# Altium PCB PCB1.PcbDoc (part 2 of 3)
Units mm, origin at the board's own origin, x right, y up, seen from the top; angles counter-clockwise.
Board outline 200.72 x 147.2 mm, 4 copper layers (L1 - TOP, L2 - GND, L3 - PWR, L4 - BOTTOM), stack 1.251 mm thick; 298 components, 161 nets, 911 pads, 474 vias.
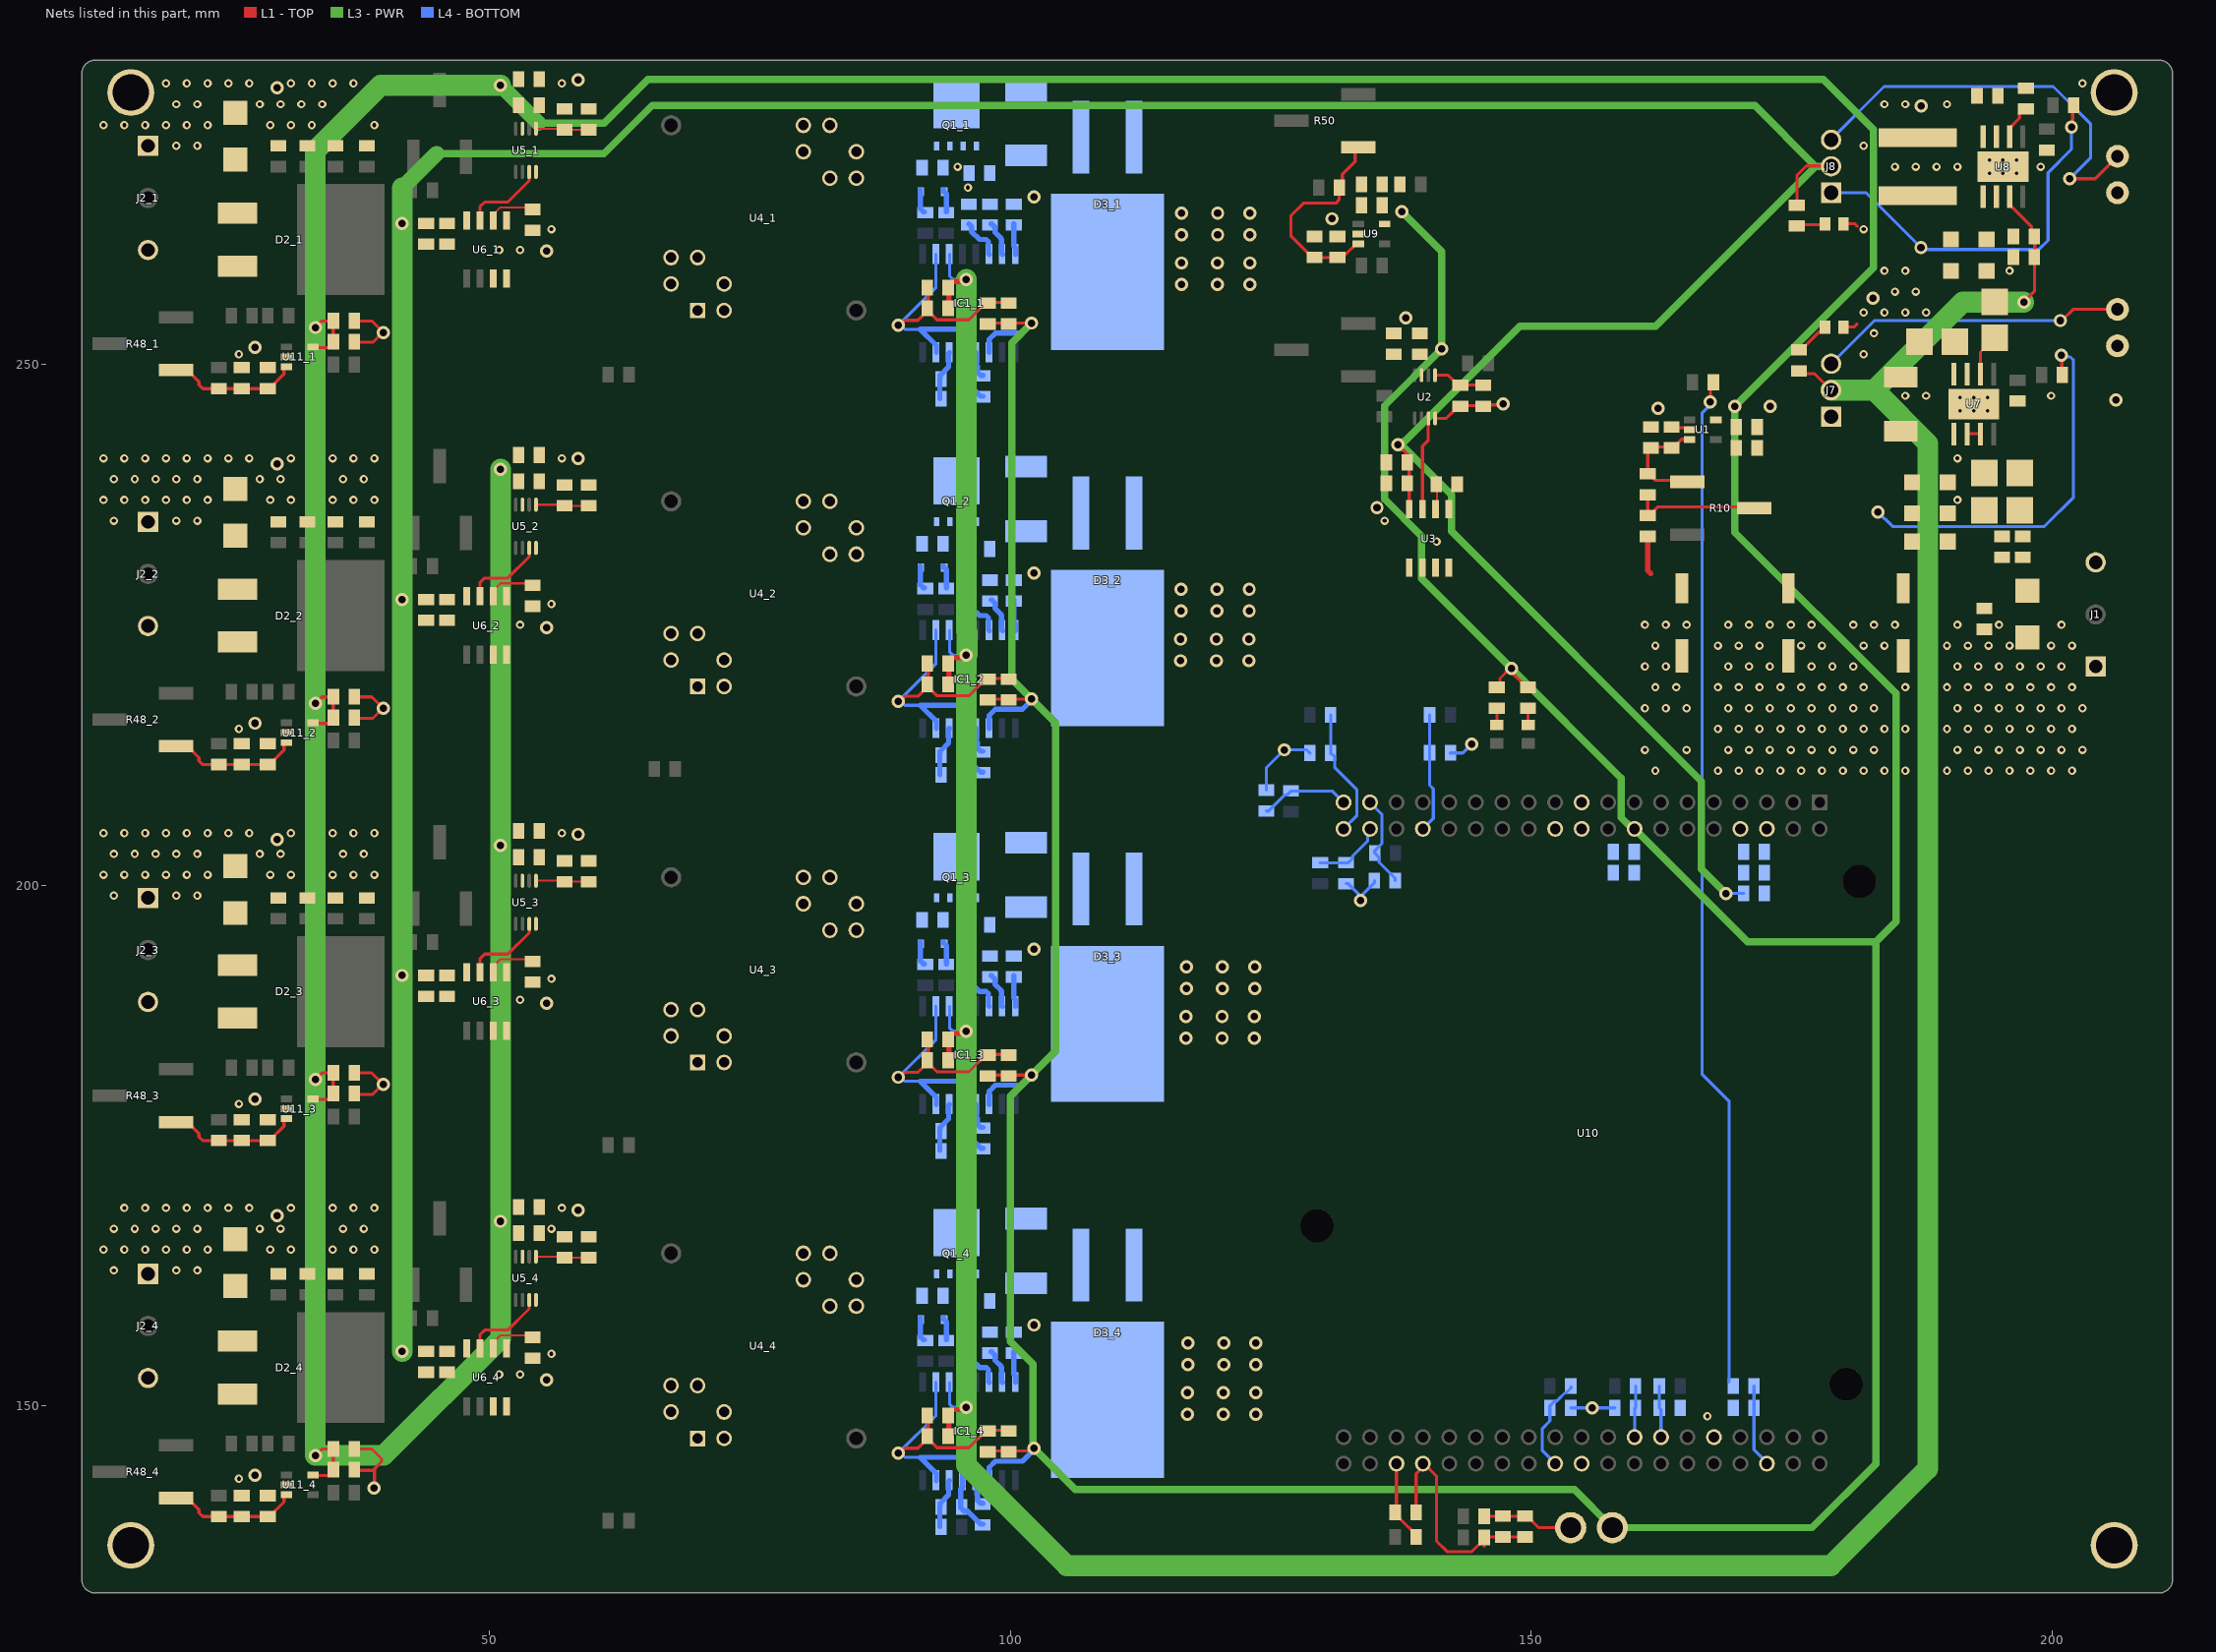
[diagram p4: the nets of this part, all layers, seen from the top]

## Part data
C1 C2 C3: "22uF 100V 121mA@120Hz ±20% SMD, D8xL10mm Aluminum Electrolytic Capacitors - SMD ROHS", Case/Package=3333, Leakage Current=66µA, Manufacturer="KYOCERA AVX", Manufacturer Part Number=UUX2A220MNL6GS, Max Operating Temperature=105°C, Min Operating Temperature=-55°C, Ratings=AEC-Q200, Ripple Current=121mA, Tolerance=20%, Voltage Rating=100V
C4 C5 C6 C7 C8 C9 C10 C11 C12 C13 C14 C15 C16 C17 C18_1 C18_2 C18_3 C18_4 C19_1 C19_2 C19_3 C19_4 C20_1 C20_2 C20_3 C20_4 C21_1 C21_2 C21_3 C21_4 C22_1 C22_2 C22_3 C22_4 C23_1 C23_2 C23_3 C23_4 C24_1 C24_2 C24_3 C24_4 C25_1 C25_2 C25_3 C25_4 C26_1 C26_2 C26_3 C26_4 C27_1 C27_2 C27_3 C27_4 C28_1 C28_2 C28_3 C28_4 C29_1 C29_2 C29_3 C29_4 C30_1 C30_2 C30_3 C30_4 C31_1 C31_2 C31_3 C31_4 C32_1 C32_2 C32_3 C32_4 C33_1 C33_2 C33_3 C33_4 C34_1 C34_2 C34_3 C34_4 C35_1 C35_2 C35_3 C35_4 C36_1 C36_2 C36_3 C36_4 C37_1 C37_2 C37_3 C37_4 C38_1 C38_2 C38_3 C38_4 C39 C40 C41 C42 C43 C44 C45 C46 C47 C48 C49 C50 C51 C52 C53 C54 C55 C56 C57 C58 C59 C60: "C0G Ceramic Smd Ceramic Capacitor"
D1: library part TVS_DIODE, "DIODO SMB"
D2_1 D2_2 D2_3 D2_4: "Rectifier Diode Schottky 40V 20A 3-Pin(2+Tab) D2PAK T/R", Manufacturer=Diotec, Manufacturer Lifecycle Status=ACTIVE, Manufacturer Part Number=SK2040YD2R
D3_1 D3_2 D3_3 D3_4 D5_1 D5_2 D5_3 D5_4: "DIODO SMB"
D4_1 D4_2 D4_3 D4_4: "Schottky Barrier Diode, 2-Pin SOD-323, Pb-Free, Tape and Reel", Manufacturer="On Semiconductor"
D6 D7 D8 D9: "DIODO LED 20mA 0805", Case Code (Imperial)=0805, Case Code (Metric)=2012, Color=Orange, Forward Current=25mA, Forward Voltage=2V, Lens Color=White, Manufacturer="Osram Opto", Manufacturer Part Number=LOR976-PS-1, Max Operating Temperature=85°C, Min Operating Temperature=-30°C, Package Quantity=16000, Reverse Voltage=12V, Supplier Part Number 1=475-2488-1-ND, Test Current=20mA
IC1_1 IC1_2 IC1_3 IC1_4: library part IR2110S, "500 V high-side and low-side gate driver IC with shutdown, SOIC 16W, RoHS", Case/Package=SOP, Manufacturer=Infineon, Manufacturer Part Number=IR2110STRPBF, Max Operating Temperature=125°C, Max Output current=2.5A, Max Output Voltage=20V, Max Power Dissipation=1.25W, Max Supply Current=340µA, Min Operating Temperature=-40°C, Min Output Voltage=10V, Min Supply Voltage=3.3V, Nominal Supply Voltage (DC)=15V, Output Voltage=520V, Package Quantity=1000, Supplier Part Number 1=IR2110SPBF, Temperature Grade=Automotive
J1 J2_1 J2_2 J2_3 J2_4: "Connector", Arrow Part Number=1935174, Manufacturer_Name="Phoenix Contact", Mouser Part Number=651-1935174
J3 J4: Manufacturer="CUI Devices", Manufacturer Part Number=TB005-762-02BE, Supplier Part Number 1=490-TB005-762-02BE
J7 J8: "Connector", Arrow Part Number=TSW-103-07-G-S-001, Manufacturer_Name=SAMTEC, Mouser Part Number=200-TSW10307GS001
Q1_1 Q1_2 Q1_3 Q1_4: library part BSC110N15NS5ATMA1_1, "Mosfet, N-Ch, 150V, 76A, Tdson Rohs Compliant: Yes", Continuous Drain Current=76A, Drain To Source Breakdown Voltage=150V, Drain To Source Resistance=9mΩ, Gate To Source Voltage=20V, Input Capacitace At Vds="2080pF @ 75V", Input Capacitance=2.08nF, Manufacturer=Infineon, Max Forward Diode Voltage=1.2V, Max Junction Temp=+150°C, Max Junction Temperature (Tj)=150°C, Max Power Dissipation=125W, Min Operating Temperature=-55°C, On-State Resistance=11mΩ, Package=PG-TDSON-8, Package Quantity=5000, Pulse Drain Current=304A, Temperature="-55°C to +150°C", Typ Forward Diode Voltage=0.88V
R1 R2 R3 R4 R5 R6 R7 R8 R9 R12_1 R12_2 R12_3 R12_4 R13_1 R13_2 R13_3 R13_4 R14_1 R14_2 R14_3 R14_4 R15_1 R15_2 R15_3 R15_4 R16_1 R16_2 R16_3 R16_4 R17_1 R17_2 R17_3 R17_4 R18_1 R18_2 R18_3 R18_4 R19_1 R19_2 R19_3 R19_4 R20_1 R20_2 R20_3 R20_4 R21_1 R21_2 R21_3 R21_4 R22_1 R22_2 R22_3 R22_4 R23_1 R23_2 R23_3 R23_4 R24_1 R24_2 R24_3 R24_4 R25_1 R25_2 R25_3 R25_4 R26_1 R26_2 R26_3 R26_4 R27_1 R27_2 R27_3 R27_4 R28_1 R28_2 R28_3 R28_4 R30_1 R30_2 R30_3 R30_4 R31 R32 R33 R34 R35 R36 R37 R38 R39 R40 R41 R42 R43 R44 R45: "SMD 0805 RESISTOR"
R10 R11 R48_1 R48_2 R48_3 R48_4 R50: library part TRIMPOT_3361_14INCH, "Trimmer, Cermet, 0.5W, 100000ohm, 300V, 10% +/-Tol, 100ppm/Cel, 1 Turn(s), 2826", Case/Package=2826, Color=Natural, Manufacturer=Bourns, Manufacturer Part Number=3361P-1-503GLF, Max Operating Temperature=125°C, Max Power Dissipation=500mW, Min Operating Temperature=-55°C, Supplier Part Number=1814483, Temperature Coefficient=100ppm/°C, Tolerance=10%, Voltage Rating=300V
R46: library part R_FL, "Resistor for flying wires"
R47_1 R47_2 R47_3 R47_4: "SMD 2512 RESISTOR"
R49_1 R49_2 R49_3 R49_4: library part TRIMPOT_3361_14INCH, "Trimmer, Cermet, 0.5W, 1000ohm, 300V, 10% +/-Tol, 100ppm/Cel, 1 Turn(s), 2619", Case/Package=2826, Color=Natural, Manufacturer=Bourns, Manufacturer Part Number=3361P-1-503GLF, Max Operating Temperature=125°C, Max Power Dissipation=500mW, Min Operating Temperature=-55°C, Supplier Part Number=1814483, Temperature Coefficient=100ppm/°C, Tolerance=10%, Voltage Rating=300V
U1: library part TLV9151_SOT23-5, "Operational Amplifier, 1 Func, 750uV Offset-Max", Manufacturer="Texas Instruments", Manufacturer Part Number=TLV9151IDBVR, Supplier Part Number 1=296-TLV9151IDBVRCT-ND
U2 U5_1 U5_2 U5_3 U5_4: library part INA326EA/250, "Precision, Low Drift, CMOS Instrumentation Amplifier 8-VSSOP -40 to 85", Case/Package=VSSOP, Input Bias Current=2nA, Input Bias Current (+/-)(Max)(nA)=2, Input Offset Voltage (Vos)=100µV, Manufacturer="Texas Instruments", Manufacturer Lifecycle Status=ACTIVE, Max Operating Temperature=85°C, Max Supply Voltage=5.5V, Min Operating Temperature=-40°C, Min Supply Voltage=2.7V, Nominal Supply Current=3.4mA, Operating Supply Current=2.4mA, Output Current per Channel=25mA, Power Supply Rejection Ratio (PSRR)=93.98dB, Quiescent Current (+/-)(Typ)(mA)=2.4, Supplier Part Number=595-INA326EA/250G4, Supplier Part Number 1=INA326EA/2K5CT-ND, Voltage Gain=80dB
U3 U6_1 U6_2 U6_3 U6_4: "66 5", Ambient Temperature Range High=85°C, Case/Package=SOIC, Current Sensing=30A, Frequency=80kHz, Manufacturer="Allegro MicroSystems", Max Junction Temperature (Tj)=165°C, Max Supply Current=13mA, Max Supply Voltage=5.5V, Min Operating Temperature=-40°C, Min Supply Voltage=4.5V, Operating Supply Current=10mA, Operating Supply Voltage=5V, Output Voltage=8V, Package Quantity=1
U4_1 U4_2 U4_3 U4_4: "Power Inductor", Arrow Part Number=B65812N1012D001, Manufacturer_Name=TDK, Mouser Part Number=871-B65812N1012D1
U7 U8: "Switching Regulator, Current-mode, 1A, 460kHz Switching Freq-Max, BICMOS, PDSO8", Manufacturer="Texas Instruments", Manufacturer Lifecycle Status=ACTIVE, Max Junction Temperature (Tj)=150°C, Max Operating Temperature=125°C, Max Supply Voltage=65V, Min Operating Temperature=-40°C, Min Supply Voltage=4.2V, Nominal Supply Current=26µA, Output Current=1A, Supplier Part Number=296-LMR36510ADDARCT-ND, Supplier Part Number 1=296-LMR36510ADDARDKR-ND, Switching Frequency=400kHz
U9 U11_1 U11_2 U11_3 U11_4: library part TLV9151_SOT23-5, "Operational Amplifier, 1 Func, 750uV Offset-Max", Manufacturer="Texas Instruments", Manufacturer Part Number=TLV9151IDBVR, Supplier Part Number 1=595-TLV9151IDBVR
U10: library part NUCLEO-F072RB, "STM32F072RB, mbed-Enabled Development Nucleo-64 STM32F0 ARMÂ® CortexÂ®-M0 MCU 32-Bit Embedded Evaluation Board", Package=None
U12: "Inductor Power Shielded Wirewound 47uH 30% 100KHz 14Q-Factor Ferrite 1.2A 0.177Ohm DCR 3131 T/R", Arrow Part Number=B65812N1012D001, Case/Package=3131, Current Rating=1.2A, DC Resistance (DCR)=177mΩ, Inductance Tolerance=30%, Manufacturer=Bourns, Manufacturer Part Number=SRU8028-470Y, Manufacturer_Name=TDK, Max Operating Temperature=125°C, Min Operating Temperature=-40°C, Mouser Part Number=871-B65812N1012D1, Saturation Current=1A, Self Resonant Frequency=12MHz, Test Frequency=100kHz
U13: library part NRS8040T220MJGJ, "Shielded Wirewound Inductor 22uH 20% 2.6A 85.8mΩ SMD Automotive", Case/Package=Nonstandard, Current Rating=2.2A, DC Resistance (DCR)=85.8mR, Inductance=22uH, Max Operating Temperature=125°C, Min Operating Temperature=-40°C, Package Quantity=1000, Ratings=AEC-Q200, Resistor Type=Wirewound, Saturation Current=2.4A, Self Resonant Frequency=13MHz, Test Frequency=100kHz, Tolerance=20%

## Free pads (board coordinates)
  round 4.5 hole 3.5: MH(15.55,136.6) MH(15.55,276.125) MH(205.975,136.6) MH(205.975,276.125)

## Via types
v1: diameter 0.8, hole 0.4, L1 - TOP to L4 - BOTTOM, tented both sides, 312 vias
v2: diameter 1.27, hole 0.711, L1 - TOP to L4 - BOTTOM, 150 vias
v3: diameter 0.63, hole 0.33, L1 - TOP to L4 - BOTTOM, 12 vias

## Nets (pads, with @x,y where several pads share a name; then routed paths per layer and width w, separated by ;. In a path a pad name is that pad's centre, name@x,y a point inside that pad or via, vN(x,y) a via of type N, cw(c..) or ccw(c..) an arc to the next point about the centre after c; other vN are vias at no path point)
3V3: C7.1 C8.1 C11.1 C12.1 C23_1.1 C23_2.1 C23_3.1 C23_4.1 C24_1.1 C24_2.1 C24_3.1 C24_4.1 C25_1.1 C25_2.1 C25_3.1 C25_4.1 C26_1.1 C26_2.1 C26_3.1 C26_4.1 C31_1.2 C31_2.2 C31_3.2 C31_4.2 C32_1.2 C32_2.2 C32_3.2 C32_4.2 C47.1 C48.1 C57.2 C58.2 IC1_1.11 IC1_2.11 IC1_3.11 IC1_4.11 R33.2 R40.1 R43.1 R46.1 U1.5 U2.7 U5_1.7 U5_2.7 U5_3.7 U5_4.7 U9.5 U10.CN7_16 U11_1.5 U11_2.5 U11_3.5 U11_4.5 | length 908
  L1 - TOP w0.3: U11_4.5@33.098,143.309 34.683,143.309 34.983,143.609 34.983,145.856 33.907,145.856 33.282,145.231 v2(33.258,145.231) ; U11_3.5@33.098,179.419 34.683,179.419 34.983,179.719 34.983,181.966 33.907,181.966 33.282,181.341 v2(33.258,181.341) ; U11_2.5@33.098,215.529 34.683,215.529 34.983,215.829 34.983,218.076 33.907,218.076 33.282,217.451 v2(33.258,217.451) ; U11_1.5@33.098,251.639 34.683,251.639 34.983,251.939 34.983,254.186 33.907,254.186 33.282,253.561 v2(33.258,253.561) ; C31_4.2@97.833,145.656 99.858,145.656 cw(c99.858,145.631) C32_4.2@99.883,145.631 ; C31_3.2@97.833,181.766 C32_3.2@99.858,181.766 ; C31_2.2@97.833,217.876 C32_2.2@99.858,217.876 ; C31_1.2@97.833,253.986 C32_1.2@99.858,253.986 ; C31_3.2@97.858,181.766 C32_3.2@99.858,181.766 ; C31_2.2@97.858,217.876 C32_2.2@99.858,217.876 ; C31_1.2@97.858,253.986 C32_1.2@99.858,253.986 ; C32_4.2@99.883,145.656 101.623,145.656 101.689,145.722 102.099,145.722 v2(102.284,145.907) ; C32_3.2@99.883,181.741 ccw(c99.858,181.741) C32_3.2@99.858,181.766 ; C32_2.2@99.883,217.851 ccw(c99.858,217.851) C32_2.2@99.858,217.876 ; C32_1.2@99.883,253.961 ccw(c99.858,253.961) C32_1.2@99.858,253.986 ; v2(102.033,181.766) C32_3.2@99.858,181.766 ; v2(102.033,217.876) C32_2.2@99.858,217.876 ; v2(102.033,253.986) C32_1.2@99.858,253.986 ; R43.1@146.708,219.046 147,219.338 147,219.849 147.951,220.8 v2(148.125,220.8) 148.311,220.614 148.311,220.255 149.096,219.469 149.096,219.446 149.496,219.046 R40.1@149.708,219.046
  L3 - PWR w0.7: 54.665,273.2 61,273.2 65.2,277.4 178.051,277.4 182.875,272.576 182.875,259.3 v2(169.55,245.975) 169.55,233.877 185.025,218.402 185.025,196.5 183.1,194.575 ; v2(102.033,253.986) 100.125,252.078 100.125,219.784 v2(102.033,217.876) 104.35,215.559 104.35,184.083 v2(102.033,181.766) 100,179.733 100,156.175 102.175,154 102.175,146.016 106.241,141.95 154.15,141.95 R46.1@157.8,138.3 176.975,138.3 183.1,144.425 183.1,194.575 ; v2(137.575,264.7) 141.4,260.875 v2(141.4,251.5) 135.95,246.05 135.95,237.05 139.475,233.525 139.475,229.45 v2(148.125,220.8) 158.625,210.3 158.625,206.5 159.715,205.41 U10.CN7_16@159.93,205.41 170.765,194.575 183.1,194.575
  L3 - PWR w1.5: v2(51.05,276.815) 54.665,273.2
  L3 - PWR w2: v2(51.05,239.94) v2(51.05,203.83) v2(51.05,167.72) 51.05,156.45 39.831,145.231 v2(33.258,145.231) v2(33.258,181.341) v2(33.258,217.451) v2(33.258,253.561) 33.258,270.533 39.54,276.815 v2(51.05,276.815)
  L4 - BOTTOM w0.5: IC1_4.11@97.963,142.822 97.963,144.086 98.558,144.681 101.158,144.681 102.284,145.807 v2(102.284,145.907) ; IC1_3.11@97.963,178.932 97.963,180.196 98.558,180.791 101.158,180.791 102.033,181.666 v2(102.033,181.766) ; IC1_2.11@97.963,215.042 97.963,216.306 98.558,216.901 101.158,216.901 102.033,217.776 v2(102.033,217.876) ; IC1_1.11@97.963,251.152 97.963,252.416 98.558,253.011 101.158,253.011 102.033,253.886 v2(102.033,253.986)
+5V: C14.1 C15.1 C33_1.1 C33_2.1 C33_3.1 C33_4.1 C34_1.1 C34_2.1 C34_3.1 C34_4.1 J8.2 R39.2 R45.1 U3.8 U6_1.8 U6_2.8 U6_3.8 U6_4.8 | length 376.9
  L1 - TOP w0.3: v2(137.2,242.3) 138.295,241.205 U3.8@138.295,236.1 ; R45.1@175.525,265.35 175.525,268.175 176.425,269.075 J8.2@178.8,269.075
  L3 - PWR w0.7: 44.901,270.25 60.976,270.25 65.601,274.875 171.476,274.875 177.311,269.04 ; v2(137.2,242.3) v2@137.526,242.3 ; v2(168.7,199.2) 166.348,201.552 166.348,209.977 142.351,233.974 142.351,237.475 137.811,242.015 137.639,242.015 137.463,242.191 137.463,242.409 137.639,242.585 137.811,242.585 148.901,253.675 161.946,253.675 177.311,269.04 ; J8.2@178.799,269.04 177.311,269.04
  L3 - PWR w1.5: 41.6,266.949 44.901,270.25
  L3 - PWR w2: v2(41.6,155.22) v2(41.6,227.44) v2(41.6,263.55) 41.6,266.949
  L4 - BOTTOM w0.3: v2(168.7,199.2) R39.2@170.4,199.2
  other v2: 41.6,191.33
+12V: C36_1.1 C36_2.1 C36_3.1 C36_4.1 C37_1.1 C37_2.1 C37_3.1 C37_4.1 C53.2 C54.2 IC1_1.3 IC1_2.3 IC1_3.3 IC1_4.3 J7.2 R41.1 U8.2 U8.3 | length 387.9
  L1 - TOP w0.3: R41.1@175.7,249.4 175.984,249.116 177.224,249.116 J7.2@178.8,247.54 ; U8.3@195.985,266.125 195.985,265.283 198.054,263.214 198.054,262.546 198.35,262.25 198.35,260.25 198.325,260.225 198.325,257.025 v2(197.3,256)
  L1 - TOP w0.5: C36_4.1@94.083,147.131 94.108,147.156 94.108,149.106 C37_4.1@94.133,149.131 ; C36_3.1@94.083,183.241 94.108,183.266 94.108,185.216 C37_3.1@94.133,185.241 ; C36_2.1@94.083,219.351 94.108,219.376 94.108,221.326 C37_2.1@94.133,221.351 ; C36_1.1@94.083,255.461 94.108,255.486 94.108,257.436 C37_1.1@94.133,257.461 ; C37_4.1@94.133,149.343 94.433,149.643 95.337,149.643 95.55,149.856 v2(95.758,149.856) ; C37_3.1@94.133,185.453 94.433,185.753 95.337,185.753 95.55,185.966 v2(95.758,185.966) ; C37_2.1@94.133,221.563 94.433,221.863 95.337,221.863 95.55,222.076 v2(95.758,222.076) ; C37_1.1@94.133,257.673 94.433,257.973 95.337,257.973 95.55,258.186 v2(95.758,258.186)
  L3 - PWR w2: v2(95.758,258.186) 95.758,224.392 95.85,224.3 95.85,222.168 v2(95.758,222.076) v2(95.758,185.966) v2(95.758,149.856) 95.758,144.292 105.4,134.65 178.775,134.65 188.075,143.95 188.075,239.45 188.075,242.43 182.965,247.54 ; J7.2@178.8,247.54 182.965,247.54 ; v2(197.3,256) 191.425,256 182.965,247.54
  L4 - BOTTOM w0.3: IC1_4.3@94.153,152.246 94.153,150.186 94.483,149.856 v2(95.758,149.856) ; IC1_3.3@94.153,188.356 94.153,186.296 94.483,185.966 v2(95.758,185.966) ; IC1_2.3@94.153,224.466 94.153,222.406 94.483,222.076 v2(95.758,222.076) ; IC1_1.3@94.153,260.576 94.153,258.516 94.483,258.186 v2(95.758,258.186)
CO_STACK_IN: D3_1.3 D3_2.3 D3_3.3 D3_4.3 U3.1 U3.2
  other v2: 117,149.175 120.45,149.175 123.55,149.175 117,151.25 120.45,151.25 123.55,151.25 117.025,153.95 120.475,153.95 123.575,153.95 117.025,156.025 120.475,156.025 123.575,156.025 116.875,185.3 120.325,185.3 123.425,185.3 116.875,187.375 120.325,187.375 123.425,187.375 116.9,190.075 120.35,190.075 123.45,190.075 116.9,192.15 120.35,192.15 123.45,192.15 116.35,221.55 119.8,221.55 122.9,221.55 116.35,223.625 119.8,223.625 122.9,223.625 116.375,226.325 119.825,226.325 122.925,226.325 116.375,228.4 119.825,228.4 122.925,228.4 116.425,257.675 119.875,257.675 122.975,257.675 116.425,259.75 119.875,259.75 122.975,259.75 116.45,262.45 119.9,262.45 123,262.45 116.45,264.525 119.9,264.525 123,264.525
GND: C1.2 C2.2 C3.2 C4.2 C5.2 C6.2 C7.2 C8.2 C9.2 C10.2 C11.2 C12.2 C13.2 C14.2 C15.2 C16.2 C17.2 C18_1.2 C18_2.2 C18_3.2 C18_4.2 C19_1.2 C19_2.2 C19_3.2 C19_4.2 C20_1.2 C20_2.2 C20_3.2 C20_4.2 C21_1.2 C21_2.2 C21_3.2 C21_4.2 C22_1.2 C22_2.2 C22_3.2 C22_4.2 C23_1.2 C23_2.2 C23_3.2 C23_4.2 C24_1.2 C24_2.2 C24_3.2 C24_4.2 C25_1.2 C25_2.2 C25_3.2 C25_4.2 C26_1.2 C26_2.2 C26_3.2 C26_4.2 C27_1.2 C27_2.2 C27_3.2 C27_4.2 C28_1.2 C28_2.2 C28_3.2 C28_4.2 C29_1.2 C29_2.2 C29_3.2 C29_4.2 C30_1.2 C30_2.2 C30_3.2 C30_4.2 C31_1.1 C31_2.1 C31_3.1 C31_4.1 C32_1.1 C32_2.1 C32_3.1 C32_4.1 C33_1.2 C33_2.2 C33_3.2 C33_4.2 C34_1.2 C34_2.2 C34_3.2 C34_4.2 C35_1.2 C35_2.2 C35_3.2 C35_4.2 C36_1.2 C36_2.2 C36_3.2 C36_4.2 C37_1.2 C37_2.2 C37_3.2 C37_4.2 C38_1.2 C38_2.2 C38_3.2 C38_4.2 C40.1 C41.1 C42.1 C43.1 C44.1 C45.1 C47.2 C48.2 C49.1 C50.2 C51.2 C52.1 C53.1 C54.1 C55.1 C56.1 C57.1 C58.1 C59.2 C60.2 D1.A D5_1.A D5_2.A D5_3.A D5_4.A D7.K D9.K IC1_1.2 IC1_1.13 IC1_1.15 IC1_2.2 IC1_2.13 IC1_2.15 IC1_3.2 IC1_3.13 IC1_3.15 IC1_4.2 IC1_4.13 IC1_4.15 J1.1 J2_1.1 J2_2.1 J2_3.1 J2_4.1 J3.2 J4.2 pad.MH Q1_1.1 Q1_1.2 Q1_1.3 Q1_2.1 Q1_2.2 Q1_2.3 Q1_3.1 Q1_3.2 Q1_3.3 Q1_4.1 Q1_4.2 Q1_4.3 R5.1 R9.2 R15_1.2 R15_2.2 R15_3.2 R15_4.2 R24_1.1 R24_2.1 R24_3.1 R24_4.1 R25_1.2 R25_2.2 R25_3.2 R25_4.2 R26_1.1 R26_2.1 R26_3.1 R26_4.1 R27_1.1 R27_2.1 R27_3.1 R27_4.1 R28_1.1 R28_2.1 R28_3.1 R28_4.1 R30_1.1 R30_2.1 R30_3.1 R30_4.1 R32.1 R37.1 R38.1 R44.2 U1.2 U2.4 U3.5 U5_1.4 U5_2.4 U5_3.4 U5_4.4 U6_1.5 U6_2.5 U6_3.5 U6_4.5 U7.1 U7.9 U8.1 U8.9 U9.2 U10.CN7_8 U10.CN7_19 U10.CN7_20 U10.CN7_22 U10.CN10_9 U10.CN10_20 U10.CN10_32 U11_1.2 U11_2.2 U11_3.2 U11_4.2 | length 237.8
  L1 - TOP w0.3: C23_4.2@36.983,143.806 38.774,143.806 38.879,143.91 ; C25_4.2@36.983,145.856 38.683,145.856 39.629,144.91 39.629,144.661 38.879,143.91 ; C23_3.2@36.983,179.916 38.774,179.916 39.724,180.866 v2(39.783,180.866) 38.683,181.966 C25_3.2@36.983,181.966 ; C23_2.2@36.983,216.026 38.774,216.026 39.724,216.976 v2(39.783,216.976) 38.683,218.076 C25_2.2@36.983,218.076 ; C23_1.2@36.983,252.136 38.774,252.136 39.724,253.086 v2(39.783,253.086) 38.683,254.186 C25_1.2@36.983,254.186 ; v2(38.878,142.101) 38.95,142.173 38.95,143.839 38.879,143.91 ; v2(89.225,145.445) 89.411,145.445 89.886,145.92 91.137,145.92 C36_4.2@92.075,146.858 ; v2(89.225,181.555) 89.411,181.555 89.886,182.03 91.137,182.03 C36_3.2@92.075,182.968 ; v2(89.225,217.665) 89.411,217.665 89.886,218.14 91.137,218.14 C36_2.2@92.075,219.078 ; v2(89.225,253.775) 89.411,253.775 89.886,254.25 91.137,254.25 C36_1.2@92.075,255.188 ; C36_4.2@92.075,147.106 C36_4.2@92.075,146.858 ; C36_3.2@92.075,183.216 C36_3.2@92.075,182.968 ; C36_2.2@92.075,219.326 C36_2.2@92.075,219.078 ; C36_1.2@92.075,255.436 C36_1.2@92.075,255.188 ; C36_4.2@92.083,147.131 92.108,147.156 92.108,149.106 C37_4.2@92.133,149.131 ; C36_3.2@92.083,183.241 92.108,183.266 92.108,185.216 C37_3.2@92.133,185.241 ; C36_2.2@92.083,219.351 92.108,219.376 92.108,221.326 C37_2.2@92.133,221.351 ; C36_1.2@92.083,255.461 92.108,255.486 92.108,257.436 C37_1.2@92.133,257.461 ; C32_4.1@99.883,147.631 99.87,147.644 97.687,147.644 96.011,145.968 92.965,145.968 C36_4.2@92.075,146.858 ; C32_3.1@99.883,183.741 99.87,183.754 97.687,183.754 96.011,182.078 92.965,182.078 C36_3.2@92.075,182.968 ; C32_2.1@99.883,219.851 99.87,219.864 97.687,219.864 96.011,218.188 92.965,218.188 C36_2.2@92.075,219.078 ; C32_1.1@99.883,255.961 99.87,255.974 97.687,255.974 96.011,254.298 92.965,254.298 C36_1.2@92.075,255.188 ; C27_4.2@138.95,139.75 138.95,143.459 139.61,144.119 U10.CN10_32@139.61,144.45 ; U10.CN10_32@139.66,144.5 140.91,143.25 140.91,137.016 141.926,136 144.312,136 C60.2@145.5,137.188 ; U2.4@140.775,244.825 141.85,244.825 142.671,245.646 142.671,245.75 142.971,246.05 145.375,246.05 145.45,246.125 147.225,246.125 v2(147.3,246.2) ; 145.5,136.507 C60.2@145.5,136.719 ; C60.2@145.5,137.4 R44.2@149.4,137.4 ; C9.2@163.489,244.077 163.636,243.93 165.192,243.93 U1.2@165.267,243.855 ; D7.K@179.989,253.6 181,253.6 181.3,253.9 ; D9.K@179.989,263.525 181.075,263.525 181.325,263.275
  L4 - BOTTOM w0.3: 91.337,145.059 89.874,145.059 89.487,145.445 v2(89.225,145.445) 92.85,149.07 IC1_4.2@92.85,152.282 ; 91.337,181.169 89.874,181.169 89.487,181.555 v2(89.225,181.555) 92.85,185.18 IC1_3.2@92.85,188.392 ; 91.337,217.279 89.874,217.279 89.487,217.665 v2(89.225,217.665) 92.85,221.29 IC1_2.2@92.85,224.502 ; 91.337,253.389 89.874,253.389 89.487,253.775 v2(89.225,253.775) 92.85,257.4 IC1_1.2@92.85,260.612 ; C29_4.2@124.578,209.125 124.578,211.291 126.287,213 128.45,213 C29_1.2@128.75,212.7 ; C29_2.2@132.225,200.149 132.437,200.149 133.439,199.147 133.439,198.711 v2(133.625,198.525) 133.811,198.711 133.811,199.099 134.95,200.238 C29_3.2@134.95,200.45 ; C27_1.2@142.25,212.703 143.428,212.703 v2(144.275,213.55) ; C13.2@153.8,149.8 v2(155.85,149.8) C27_3.2@158.025,149.8
  L4 - BOTTOM w0.5: IC1_4.15@92.883,142.822 92.883,143.513 91.337,145.059 94.855,145.059 95.423,144.491 95.423,142.185 95.241,142.003 C38_4.2@95.241,140.406 ; IC1_3.15@92.883,178.932 92.883,179.622 91.337,181.169 94.855,181.169 95.423,180.601 95.423,178.295 95.241,178.113 C38_3.2@95.241,176.516 ; IC1_2.15@92.883,215.042 92.883,215.732 91.337,217.279 94.855,217.279 95.423,216.711 95.423,214.405 95.241,214.223 C38_2.2@95.241,212.626 ; IC1_1.15@92.883,251.152 92.883,251.842 91.337,253.389 94.855,253.389 95.423,252.821 95.423,250.515 95.241,250.333 C38_1.2@95.241,248.736 ; C38_4.2@95.241,140.194 95.541,139.894 95.883,139.894 97.146,138.631 R30_4.1@97.358,138.631 ; C38_3.2@95.241,176.304 95.541,176.004 95.883,176.004 97.146,174.741 R30_3.1@97.358,174.741 ; C38_2.2@95.241,212.414 95.541,212.114 95.883,212.114 97.146,210.851 R30_2.1@97.358,210.851 ; C38_1.2@95.241,248.524 95.541,248.224 95.883,248.224 97.146,246.961 R30_1.1@97.358,246.961
  other v1: 25.925,143 166.925,149 50.925,153 52.925,153 55.925,155 13.925,163 19.925,163 21.925,163 12.925,165 14.925,165 16.925,165 18.925,165 20.925,165 22.925,165 28.925,165 30.925,165 34.925,165 36.925,165 38.925,165 13.925,167 15.925,167 17.925,167 19.925,167 21.925,167 27.925,167 29.925,167 35.925,167 37.925,167 55.925,167 14.925,169 16.925,169 18.925,169 20.925,169 22.925,169 24.925,169 26.925,169 30.925,169 34.925,169 36.925,169 38.925,169 56.925,169 25.925,179 52.925,189 55.925,191 13.925,199 19.925,199 21.925,199 12.925,201 14.925,201 16.925,201 18.925,201 20.925,201 22.925,201 28.925,201 30.925,201 34.925,201 36.925,201 38.925,201 13.925,203 15.925,203 17.925,203 19.925,203 21.925,203 27.925,203 29.925,203 35.925,203 37.925,203 12.925,205 14.925,205 16.925,205 18.925,205 20.925,205 22.925,205 24.925,205 26.925,205 30.925,205 34.925,205 36.925,205 38.925,205 56.925,205 161.925,211 167.925,211 169.925,211 171.925,211 173.925,211 175.925,211 177.925,211 179.925,211 181.925,211 183.925,211 185.925,211 189.925,211 191.925,211 193.925,211 195.925,211 197.925,211 199.925,211 201.925,211 160.925,213 164.925,213 168.925,213 170.925,213 172.925,213 174.925,213 176.925,213 178.925,213 180.925,213 182.925,213 190.925,213 192.925,213 194.925,213 196.925,213 198.925,213 200.925,213 202.925,213 25.925,215 167.925,215 169.925,215 171.925,215 173.925,215 175.925,215 177.925,215 179.925,215 181.925,215 183.925,215 185.925,215 189.925,215 191.925,215 193.925,215 195.925,215 197.925,215 199.925,215 201.925,215 160.925,217 162.925,217 164.925,217 168.925,217 170.925,217 172.925,217 174.925,217 176.925,217 178.925,217 180.925,217 182.925,217 190.925,217 192.925,217 194.925,217 196.925,217 198.925,217 200.925,217 202.925,217 161.925,219 163.925,219 167.925,219 169.925,219 171.925,219 173.925,219 175.925,219 177.925,219 179.925,219 181.925,219 185.925,219 189.925,219 191.925,219 193.925,219 195.925,219 197.925,219 199.925,219 201.925,219 160.925,221 162.925,221 168.925,221 170.925,221 172.925,221 176.925,221 178.925,221 180.925,221 190.925,221 192.925,221 194.925,221 196.925,221 198.925,221 200.925,221 161.925,223 167.925,223 169.925,223 171.925,223 175.925,223 177.925,223 181.925,223 183.925,223 189.925,223 191.925,223 193.925,223 195.925,223 199.925,223 201.925,223 52.925,225 160.925,225 162.925,225 164.925,225 168.925,225 170.925,225 172.925,225 174.925,225 176.925,225 180.925,225 182.925,225 184.925,225 190.925,225 194.925,225 200.925,225 55.925,227 140.925,233 13.925,235 19.925,235 21.925,235 135.925,235 12.925,237 14.925,237 16.925,237 18.925,237 20.925,237 22.925,237 28.925,237 30.925,237 34.925,237 36.925,237 38.925,237 190.925,237 13.925,239 15.925,239 17.925,239 19.925,239 21.925,239 27.925,239 29.925,239 35.925,239 37.925,239 12.925,241 14.925,241 16.925,241 18.925,241 20.925,241 22.925,241 24.925,241 26.925,241 30.925,241 34.925,241 36.925,241 38.925,241 56.925,241 190.925,241 185.925,247 187.925,247 199.925,247 25.925,251 181.925,251 182.925,253 181.925,255 183.925,255 185.925,255 187.925,255 184.925,257 186.925,257 183.925,259 185.925,259 195.925,259 50.925,261 52.925,261 55.925,263 181.925,263 95.925,267 94.925,269 184.925,269 186.925,269 188.925,269 190.925,269 198.925,269 19.925,271 21.925,271 181.925,271 12.925,273 14.925,273 16.925,273 18.925,273 20.925,273 22.925,273 28.925,273 30.925,273 32.925,273 38.925,273 19.925,275 21.925,275 27.925,275 29.925,275 31.925,275 33.925,275 183.925,275 185.925,275 189.925,275 18.925,277 20.925,277 22.925,277 24.925,277 26.925,277 30.925,277 32.925,277 34.925,277 36.925,277 56.925,277 202.925,277
  other v2: 27.458,143.331 55.45,152.475 102.283,157.756 29.608,168.256 58.5,168.77 27.458,179.441 55.45,188.675 102.283,193.866 29.608,204.366 58.5,204.88 126.3,213 27.458,215.551 55.45,224.75 102.283,229.976 135.2,236.25 29.608,240.476 58.5,240.99 162.175,245.8 172.95,245.975 206.15,246.6 27.458,251.661 137.95,254.475 182.8,256.375 55.45,260.925 130.9,264 102.283,266.086 187.45,274.85 29.608,276.586 58.5,277.35
  other v3: 191.2,245.55 192.5,245.55 193.8,245.55 191.2,246.85 192.5,246.85 193.8,246.85 194,268.35 195.3,268.35 196.6,268.35 194,269.65 195.3,269.65 196.6,269.65
HALL_OUT_1: U4_1.1 U4_1.2 U4_1.3 U4_1.10 U4_1.11 U4_1.12 U6_1.3 U6_1.4
HALL_OUT_2: U4_2.1 U4_2.2 U4_2.3 U4_2.10 U4_2.11 U4_2.12 U6_2.3 U6_2.4
HALL_OUT_3: U4_3.1 U4_3.2 U4_3.3 U4_3.10 U4_3.11 U4_3.12 U6_3.3 U6_3.4
HALL_OUT_4: U4_4.1 U4_4.2 U4_4.3 U4_4.10 U4_4.11 U4_4.12 U6_4.3 U6_4.4
HALL_SENSE_1: U5_1.3 U6_1.7 | length 7.9
  L1 - TOP w0.3: U6_1.7@49.065,263.85 49.065,265.14 49.525,265.6 51.75,265.6 53.79,267.64 53.79,268.49 U5_1.3@53.8,268.5
HALL_SENSE_2: U5_2.3 U6_2.7 | length 7.9
  L1 - TOP w0.3: U6_2.7@49.065,227.74 49.065,229.03 49.525,229.49 51.75,229.49 53.79,231.53 53.79,232.38 U5_2.3@53.8,232.39
HALL_SENSE_3: U5_3.3 U6_3.7 | length 7.9
  L1 - TOP w0.3: U6_3.7@49.065,191.63 49.065,192.92 49.525,193.38 51.75,193.38 53.79,195.42 53.79,196.27 U5_3.3@53.8,196.28
HALL_SENSE_4: U5_4.3 U6_4.7 | length 7.9
  L1 - TOP w0.3: U6_4.7@49.065,155.52 49.065,156.81 49.525,157.27 51.75,157.27 53.79,159.31 53.79,160.16 U5_4.3@53.8,160.17
LIPO: C1.1 C2.1 C3.1 C4.1 C5.1 C6.1 C44.2 C45.2 D1.K J1.3 R1.2 U3.3 U3.4 U7.2 U7.3 | length 5.9
  L1 - TOP w0.3: U7.2@191.865,243.375 193.135,243.375 193.135,242.525 U7.3@193.154,242.525
  L1 - TOP w0.5: R1.2@161.2,233.5 161.2,230.2 161.5,229.9
LIPO_ISENSE_ADC: U2.3 U3.7 | length 9
  L1 - TOP w0.3: U3.7@139.565,236.1 139.565,242.165 140.125,242.725 U2.3@140.125,244.825
NetC9_1: C9.1 R2.1 R5.2 R10.1 U1.3 | length 11
  L1 - TOP w0.3: R10.1@165.05,238.88 161.912,238.88 161.412,239.38 161.2,239.38 161.2,241.82 161.457,242.077 163.489,242.077 163.701,242.077 164.451,242.827 165.192,242.827 U1.3@165.267,242.902
NetC10_1: C10.1 R4.2 U10.CN10_6 | length 7.9
  L4 - BOTTOM w0.3: R4.2@171.4,151.9 171.4,149.775 171.4,145.78 U10.CN10_6@172.68,144.5
NetC13_1: C13.1 R8.1 U10.CN10_22 | length 10.2
  L4 - BOTTOM w0.3: C13.1@151.794,149.8 151.794,148.544 151.075,147.825 151.075,145.685 U10.CN10_22@152.31,144.45 ; C13.1@151.794,150.006 C13.1@152.2,150.412 ; C13.1@151.8,149.8 151.8,150.012 C13.1@152.2,150.412 ; R8.1@153.82,151.82 153.82,151.708 153.4,151.288 153.288,151.288 152.544,150.544 ; C13.1@152.2,150.412 152.412,150.412 ; C13.1@152.2,150.412 152.412,150.412 ; 152.412,150.412 152.544,150.544 ; 152.412,150.412 152.544,150.544
NetC16_1: C16.1 U3.6 | length 2.4
  L1 - TOP w0.2: U3.6@140.835,236.1 140.95,236.215 C16.1@140.95,238.475
NetC17_1: C17.1 R9.1 U2.5 | length 5
  L1 - TOP w0.3: U2.5@140.775,248.975 142.046,248.975 142.971,248.05 143.183,248.05 C17.1@145.375,248.05
NetC22_1_1: C22_1.1 R47_1.1
NetC22_2_1: C22_2.1 R47_2.1
NetC22_3_1: C22_3.1 R47_3.1
NetC22_4_1: C22_4.1 R47_4.1
NetC27_1_1: C27_1.1 R22_1.1 U10.CN7_32 | length 11.5
  L4 - BOTTOM w0.3: U10.CN7_32@139.61,205.41 140.612,206.412 140.612,209.236 140.25,209.598 C27_1.1@140.25,212.703 R22_1.1@140.25,216.35
NetC27_2_1: C27_2.1 R22_2.1 U10.CN10_13 | length 5
  L4 - BOTTOM w0.3: R22_2.1@162.3,151.9 C27_2.1@162.3,149.8 162.47,149.63 U10.CN10_13@162.47,146.99
NetC27_3_1: C27_3.1 R22_3.1 U10.CN10_15 | length 4.9
  L4 - BOTTOM w0.3: U10.CN10_15@159.93,146.99 159.93,149.705 C27_3.1@160.025,149.8 R22_3.1@160.025,151.9
NetC27_4_1: C27_4.1 R22_4.1 U10.CN10_34 | length 8
  L1 - TOP w0.3: U10.CN10_34@137.07,144.45 137.07,139.87 C27_4.1@136.95,139.75 136.95,139.538 137.35,139.138 137.424,139.138 138.95,137.612 R22_4.1@138.95,137.4
NetC28_1_1: C28_1.1 R20_1.1 R24_1.2 R48_1.1 U11_1.3 | length 12.6
  L1 - TOP w0.3: R48_1.1@19.985,249.404 21.04,249.404 22.092,248.352 22.092,248.048 22.454,247.686 23.966,247.686 26.291,247.686 28.641,247.686 28.853,247.686 30.258,249.091 30.258,249.659 30.333,249.734 U11_1.3@30.558,249.734
NetC28_2_1: C28_2.1 R20_2.1 R24_2.2 R48_2.1 U11_2.3 | length 12.6
  L1 - TOP w0.3: R48_2.1@19.985,213.294 21.04,213.294 22.092,212.242 22.092,211.938 22.454,211.576 23.966,211.576 26.291,211.576 28.641,211.576 28.853,211.576 30.258,212.981 30.258,213.549 30.333,213.624 U11_2.3@30.558,213.624
NetC28_3_1: C28_3.1 R20_3.1 R24_3.2 R48_3.1 U11_3.3 | length 12.6
  L1 - TOP w0.3: R48_3.1@19.985,177.184 21.04,177.184 22.092,176.132 22.092,175.828 22.454,175.466 23.966,175.466 26.291,175.466 28.641,175.466 28.853,175.466 30.258,176.871 30.258,177.439 30.333,177.514 U11_3.3@30.558,177.514
NetC28_4_1: C28_4.1 R20_4.1 R24_4.2 R48_4.1 U11_4.3 | length 12.6
  L1 - TOP w0.3: R48_4.1@19.985,141.074 21.04,141.074 22.092,140.022 22.092,139.718 22.454,139.356 23.966,139.356 26.291,139.356 28.641,139.356 28.853,139.356 30.258,140.761 30.258,141.329 30.333,141.404 U11_4.3@30.558,141.404
NetC29_1_1: C29_1.1 R23_1.2 U10.CN7_38 | length 12.5
  L4 - BOTTOM w0.3: R23_1.2@130.75,216.35 C29_1.1@130.75,212.7 131.15,212.3 131.15,211.275 133.275,209.15 133.275,206.695 U10.CN7_38@131.99,205.41
NetC29_2_1: C29_2.1 R23_2.2 U10.CN7_36 | length 6.8
  L4 - BOTTOM w0.3: R23_2.2@129.75,202.149 C29_2.1@132.225,202.149 132.437,202.149 132.837,202.549 132.837,202.761 134.296,204.22 134.296,205.176 U10.CN7_36@134.53,205.41
NetC29_3_1: C29_3.1 R23_3.2 U10.CN7_35 | length 9.1
  L4 - BOTTOM w0.3: U10.CN7_35@134.53,207.95 135.675,206.805 135.675,204.003 134.975,203.303 R23_3.2@134.975,203.091 135.375,202.691 135.375,202.237 136.95,200.662 C29_3.1@136.95,200.45
NetC29_4_1: C29_4.1 R23_4.2 U10.CN7_37 | length 8.7
  L4 - BOTTOM w0.3: C29_4.1@124.578,207.125 124.79,207.125 126.315,208.65 126.55,208.65 R23_4.2@126.95,209.05 130.89,209.05 U10.CN7_37@131.99,207.95
NetC30_1_1: C30_1.1 R25_1.1 U5_1.5 | length 5.1
  L1 - TOP w0.2: U5_1.5@54.45,272.65 57.1,272.65 C30_1.1@57.2,272.55 R25_1.1@59.5,272.55
NetC30_2_1: C30_2.1 R25_2.1 U5_2.5 | length 5.1
  L1 - TOP w0.2: U5_2.5@54.45,236.54 57.1,236.54 C30_2.1@57.2,236.44 R25_2.1@59.5,236.44
NetC30_3_1: C30_3.1 R25_3.1 U5_3.5 | length 5.1
  L1 - TOP w0.2: U5_3.5@54.45,200.43 57.1,200.43 C30_3.1@57.2,200.33 R25_3.1@59.5,200.33
NetC30_4_1: C30_4.1 R25_4.1 U5_4.5 | length 5.1
  L1 - TOP w0.2: U5_4.5@54.45,164.32 57.1,164.32 C30_4.1@57.2,164.22 R25_4.1@59.5,164.22
NetC35_1_1: C35_1.1 U6_1.6 | length 4.7
  L1 - TOP w0.2: U6_1.6@50.335,263.85 50.335,264.4 51.035,265.1 53.925,265.1 C35_1.1@54.125,264.9
NetC35_2_1: C35_2.1 U6_2.6 | length 4.7
  L1 - TOP w0.2: U6_2.6@50.335,227.74 50.335,228.29 51.035,228.99 53.925,228.99 C35_2.1@54.125,228.79
NetC35_3_1: C35_3.1 U6_3.6 | length 4.7
  L1 - TOP w0.2: U6_3.6@50.335,191.63 50.335,192.18 51.035,192.88 53.925,192.88 C35_3.1@54.125,192.68
NetC35_4_1: C35_4.1 U6_4.6 | length 4.7
  L1 - TOP w0.2: U6_4.6@50.335,155.52 50.335,156.07 51.035,156.77 53.925,156.77 C35_4.1@54.125,156.57
NetC38_1_1: C38_1.1 IC1_1.14 R13_1.1 | length 4.6
  L4 - BOTTOM w0.5: R13_1.1@93.216,246.736 93.229,246.749 93.229,248.724 C38_1.1@93.241,248.736 ; C38_1.1@93.241,248.948 94.078,249.785 94.078,251.077 IC1_1.14@94.153,251.152
NetC38_2_1: C38_2.1 IC1_2.14 R13_2.1 | length 4.6
  L4 - BOTTOM w0.5: R13_2.1@93.216,210.626 93.229,210.639 93.229,212.614 C38_2.1@93.241,212.626 ; C38_2.1@93.241,212.838 94.078,213.675 94.078,214.967 IC1_2.14@94.153,215.042
NetC38_3_1: C38_3.1 IC1_3.14 R13_3.1 | length 4.6
  L4 - BOTTOM w0.5: R13_3.1@93.216,174.516 93.229,174.529 93.229,176.504 C38_3.1@93.241,176.516 ; C38_3.1@93.241,176.728 94.078,177.565 94.078,178.857 IC1_3.14@94.153,178.932
NetC38_4_1: C38_4.1 IC1_4.14 R13_4.1 | length 4.6
  L4 - BOTTOM w0.5: R13_4.1@93.216,138.406 93.229,138.419 93.229,140.394 C38_4.1@93.241,140.406 ; C38_4.1@93.241,140.618 94.078,141.455 94.078,142.747 IC1_4.14@94.153,142.822
NetC39_1: C39.1 U7.7
NetC39_2: C39.2 U7.8 U12.1
NetC40_2: C40.2 U7.6 | length 4
  L1 - TOP w0.3: U7.6@193.135,249.125 193.135,251.206 C40.2@194.5,252.571
NetC41_2: C41.2 C42.2 C43.2 J7.1 R31.2 U12.2 | length 37
  L1 - TOP w0.3: v2(200.9,250.875) 200.95,250.825 200.95,249.05 R31.2@201,249
  L4 - BOTTOM w0.3: v2(183.3,235.85) 184.705,234.445 199.275,234.445 202.075,237.245 202.075,250.435 201.782,250.728 201.047,250.728 v2(200.9,250.875)
NetC46_1: C46.1 U8.7
NetC46_2: C46.2 U8.8 U13.1
NetC49_2: C49.2 U8.6 | length 3.4
  L1 - TOP w0.3: U8.6@195.935,271.875 195.935,272.725 196.888,273.678 196.888,274.15 197.288,274.55 C49.2@197.5,274.55
NetC50_1: C50.1 C51.1 J8.1 R34.2 U13.2 | length 37.4
  L1 - TOP w0.3: v2(201.875,272.8) 201.987,272.912 201.987,274.763 R34.2@202.1,274.875
  L4 - BOTTOM w0.3: J8.1@178.8,266.5 182.175,266.5 v2(187.425,261.25) 187.625,261.05 198.75,261.05 199.625,261.925 199.625,268.425 201.875,270.675 v2(201.875,272.8)
NetC52_2: C52.2 R35.1 R37.2 R50.1 U9.3 | length 20.9
  L1 - TOP w0.3: R50.1@133.375,270.82 133.1,270.545 133.1,269.5 131.875,268.275 131.875,267.25 131.625,267 131.55,266.925 131.55,265.8 131.25,265.5 128.125,265.5 126.95,264.325 126.95,262.313 128.988,260.275 129.2,260.275 131.45,260.275 131.75,260.575 132.18,260.575 133.225,261.62 U9.3@133.45,261.62
NetC55_2: C55.2 C56.2 R39.1 U10.CN7_6
NetC59_1: C59.1 R42.2 R44.1 R46.2 | length 8.8
  L1 - TOP w0.3: R42.2@145.5,139.4 C59.1@147.3,139.4 R44.1@149.4,139.4 149.612,139.4 150.712,138.3 R46.2@153.8,138.3
NetD2_1_A: D2_1.A D5_1.K J2_1.3
NetD2_2_A: D2_2.A D5_2.K J2_2.3
NetD2_3_A: D2_3.A D5_3.K J2_3.3
NetD2_4_A: D2_4.A D5_4.K J2_4.3
NetD3_1_1,2: D3_1.1 D3_1.2 Q1_1.5-6-7-8 R47_1.2 U4_1.4 U4_1.5 U4_1.6 U4_1.7 U4_1.8 U4_1.9
NetD3_2_1,2: D3_2.1 D3_2.2 Q1_2.5-6-7-8 R47_2.2 U4_2.4 U4_2.5 U4_2.6 U4_2.7 U4_2.8 U4_2.9
NetD3_3_1,2: D3_3.1 D3_3.2 Q1_3.5-6-7-8 R47_3.2 U4_3.4 U4_3.5 U4_3.6 U4_3.7 U4_3.8 U4_3.9
NetD3_4_1,2: D3_4.1 D3_4.2 Q1_4.5-6-7-8 R47_4.2 U4_4.4 U4_4.5 U4_4.6 U4_4.7 U4_4.8 U4_4.9
NetD4_1_1: D4_1.1 R12_1.1 | length 2.2
  L4 - BOTTOM w0.5: D4_1.1@93.581,266.761 93.581,266.661 93.866,266.376 R12_1.1@93.866,264.661
NetD4_1_2: D4_1.2 Q1_1.4 R14_1.1 R15_1.1 | length 2.3
  L4 - BOTTOM w0.5: D4_1.2@91.351,266.761 91.351,264.961 91.651,264.661 R14_1.1@91.741,264.661
NetD4_2_1: D4_2.1 R12_2.1 | length 2.2
  L4 - BOTTOM w0.5: D4_2.1@93.581,230.651 93.581,230.551 93.866,230.266 R12_2.1@93.866,228.551
NetD4_2_2: D4_2.2 Q1_2.4 R14_2.1 R15_2.1 | length 2.3
  L4 - BOTTOM w0.5: D4_2.2@91.351,230.651 91.351,228.851 91.651,228.551 R14_2.1@91.741,228.551
NetD4_3_1: D4_3.1 R12_3.1 | length 2.2
  L4 - BOTTOM w0.5: D4_3.1@93.581,194.541 93.581,194.441 93.866,194.156 R12_3.1@93.866,192.441
NetD4_3_2: D4_3.2 Q1_3.4 R14_3.1 R15_3.1 | length 2.3
  L4 - BOTTOM w0.5: D4_3.2@91.351,194.541 91.351,192.741 91.651,192.441 R14_3.1@91.741,192.441
NetD4_4_1: D4_4.1 R12_4.1 | length 2.2
  L4 - BOTTOM w0.5: D4_4.1@93.581,158.431 93.581,158.331 93.866,158.046 R12_4.1@93.866,156.331
NetD4_4_2: D4_4.2 Q1_4.4 R14_4.1 R15_4.1 | length 2.3
  L4 - BOTTOM w0.5: D4_4.2@91.351,158.431 91.351,156.631 91.651,156.331 R14_4.1@91.741,156.331
NetD6_A: D6.A R40.2 | length 1.6
  L1 - TOP w0.3: D6.A@149.708,215.435 R40.2@149.708,217.046
NetD7_A: D7.A R41.2 | length 3.5
  L1 - TOP w0.3: R41.2@175.7,251.4 175.912,251.4 177.627,253.115 177.853,253.115 178.211,253.473 D7.A@178.211,253.6
NetD8_A: D8.A R43.2 | length 1.6
  L1 - TOP w0.3: D8.A@146.708,215.435 R43.2@146.708,217.046
NetD9_A: D9.A R45.2 | length 2.8
  L1 - TOP w0.3: R45.2@175.525,263.35 175.613,263.437 178.123,263.437 D9.A@178.211,263.525
NetIC1_1_6: IC1_1.6 R28_1.2 | length 4.1
  L4 - BOTTOM w0.5: R28_1.2@96.016,263.511 96.258,263.269 96.258,262.786 97.033,262.011 97.67,262.011 97.888,261.793 97.888,260.651 IC1_1.6@97.963,260.576
NetIC1_1_7: IC1_1.7 R27_1.2 | length 3.4
  L4 - BOTTOM w0.5: R27_1.2@98.166,263.511 98.208,263.511 98.508,263.211 98.508,262.711 99.108,262.111 99.108,262.061 99.158,262.011 99.158,260.651 IC1_1.7@99.233,260.576
NetIC1_1_8: IC1_1.8 R26_1.2 | length 3
  L4 - BOTTOM w0.5: R26_1.2@100.316,263.511 100.316,261.401 100.503,261.214 IC1_1.8@100.503,260.576
NetIC1_1_12: IC1_1.12 R30_1.2 | length 2.6
  L4 - BOTTOM w0.5: IC1_1.12@96.693,251.152 96.768,251.077 96.768,249.876 96.846,249.798 96.846,249.261 97.146,248.961 R30_1.2@97.358,248.961
NetIC1_2_6: IC1_2.6 R28_2.2 | length 4.1
  L4 - BOTTOM w0.5: R28_2.2@96.016,227.401 96.258,227.159 96.258,226.676 97.033,225.901 97.67,225.901 97.888,225.683 97.888,224.541 IC1_2.6@97.963,224.466
NetIC1_2_7: IC1_2.7 R27_2.2 | length 3.4
  L4 - BOTTOM w0.5: R27_2.2@98.166,227.401 98.208,227.401 98.508,227.101 98.508,226.601 99.108,226.001 99.108,225.951 99.158,225.901 99.158,224.541 IC1_2.7@99.233,224.466
NetIC1_2_8: IC1_2.8 R26_2.2 | length 3
  L4 - BOTTOM w0.5: R26_2.2@100.316,227.401 100.316,225.291 100.503,225.104 IC1_2.8@100.503,224.466
NetIC1_2_12: IC1_2.12 R30_2.2 | length 2.6
  L4 - BOTTOM w0.5: IC1_2.12@96.693,215.042 96.768,214.967 96.768,213.766 96.846,213.688 96.846,213.151 97.146,212.851 R30_2.2@97.358,212.851
NetIC1_3_6: IC1_3.6 R28_3.2 | length 4.1
  L4 - BOTTOM w0.5: R28_3.2@96.016,191.291 96.258,191.049 96.258,190.566 97.033,189.791 97.67,189.791 97.888,189.573 97.888,188.431 IC1_3.6@97.963,188.356
NetIC1_3_7: IC1_3.7 R27_3.2 | length 3.4
  L4 - BOTTOM w0.5: R27_3.2@98.166,191.291 98.208,191.291 98.508,190.991 98.508,190.491 99.108,189.891 99.108,189.841 99.158,189.791 99.158,188.431 IC1_3.7@99.233,188.356
NetIC1_3_8: IC1_3.8 R26_3.2 | length 3
  L4 - BOTTOM w0.5: R26_3.2@100.316,191.291 100.316,189.181 100.503,188.994 IC1_3.8@100.503,188.356
NetIC1_3_12: IC1_3.12 R30_3.2 | length 2.6
  L4 - BOTTOM w0.5: IC1_3.12@96.693,178.932 96.768,178.857 96.768,177.656 96.846,177.578 96.846,177.041 97.146,176.741 R30_3.2@97.358,176.741
NetIC1_4_6: IC1_4.6 R28_4.2 | length 4.1
  L4 - BOTTOM w0.5: R28_4.2@96.016,155.181 96.258,154.939 96.258,154.456 97.033,153.681 97.67,153.681 97.888,153.463 97.888,152.321 IC1_4.6@97.963,152.246
NetIC1_4_7: IC1_4.7 R27_4.2 | length 3.4
  L4 - BOTTOM w0.5: R27_4.2@98.166,155.181 98.208,155.181 98.508,154.881 98.508,154.381 99.108,153.781 99.108,153.731 99.158,153.681 99.158,152.321 IC1_4.7@99.233,152.246
NetIC1_4_8: IC1_4.8 R26_4.2 | length 3
  L4 - BOTTOM w0.5: R26_4.2@100.316,155.181 100.316,153.071 100.503,152.884 IC1_4.8@100.503,152.246
NetIC1_4_12: IC1_4.12 R30_4.2 | length 2.6
  L4 - BOTTOM w0.5: IC1_4.12@96.693,142.822 96.768,142.747 96.768,141.546 96.846,141.468 96.846,140.931 97.146,140.631 R30_4.2@97.358,140.631
NetJ3_1: J3.1 J7.3 | length 29.7
  L1 - TOP w0.3: v2(200.825,254.225) 200.962,254.225 202.037,255.3 J3.1@206.325,255.3
  L4 - BOTTOM w0.3: J7.3@178.8,250.065 182.96,254.225 v2(200.825,254.225)
NetJ4_1: J4.1 J8.3 | length 40.1
  L1 - TOP w0.3: v2(201.7,267.85) 204.175,267.85 J4.1@206.325,270
  L4 - BOTTOM w0.3: J8.3@178.8,271.615 183.885,276.7 200.125,276.7 203.725,273.1 203.725,269.875 v2(201.7,267.85)
NetR1_1: R1.1 R2.2 R10.2 | length 12.4
  L1 - TOP w0.3: R2.2@161.2,237.38 161.2,235.58 161.412,235.58 162.172,236.34 R10.2@171.45,236.34
NetR3_1: R3.1 R4.1 | length 97.5
  L1 - TOP w0.3: v2(167.2,246.4) 167.2,248 R3.1@167.5,248.3
  L4 - BOTTOM w0.3: v2(167.2,246.4) 167.2,246.138 166.4,245.338 166.4,181.863 169,179.263 R4.1@169,152.3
